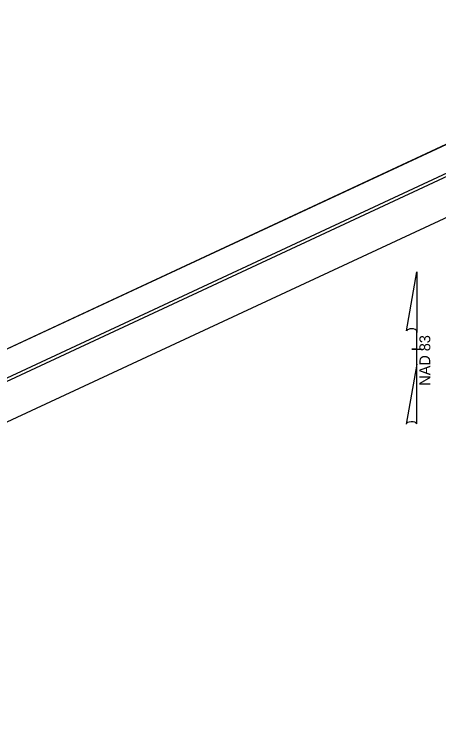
# Model space of a CAD drawing. Extents: x 2321825 to 2323872, y 921700 to 923436.
# Drawn here: x 2322864 to 2323189, y 922857 to 923403 of the extents above; entities that cross this region are included whole.
import ezdxf

# ---------------------------------------------------------------- set-up
doc = ezdxf.new("R2010")
doc.units = 0
for name, color, linetype in [('Prop North Arrow NAD83 for Plan Sheets CELL', 7, 'Continuous'), ('Sheet Cutting Line CELL', 7, 'Continuous'), ('Sheet Layout Plan Border', 7, 'Continuous'), ('Sheet Plan And Profile CELL', 7, 'Continuous'), ('Sheet Plot Border Inside CELL', 7, 'Continuous'), ('Sheet Plot Border Outside CELL', 7, 'Continuous')]:
    doc.layers.add(name, color=color, linetype=linetype)

msp = doc.modelspace()

# ---------------------------------------------------------------- linework, layer by layer
at = {"layer": 'Prop North Arrow NAD83 for Plan Sheets CELL'}
for p, q in [((2323164.49, 923160.58), (2323172.49, 923205.77)), ((2323172.54, 923205.77), (2323172.49, 923205.77)), ((2323172.54, 923205.77), (2323172.49, 923205.77)), ((2323172.54, 923205.77), (2323172.53, 923159.17)), ((2323172.53, 923134.99), (2323172.53, 923160.53)), ((2323172.53, 923159.17), (2323172.53, 923160.49)), ((2323168.63, 923146.3), (2323168.58, 923146.3)), ((2323172.09, 923146.3), (2323168.63, 923146.3)), ((2323168.68, 923146.3), (2323176.48, 923146.3)), ((2323172.53, 923134.99), (2323164.38, 923088.92)), ((2323172.57, 923089.12), (2323172.53, 923134.99))]:
    msp.add_line(p, q, dxfattribs=at)
for centre, start_param, end_param in [((2323168.52, 923160.1), 0.216388, 2.908219), ((2323168.51, 923088.76), 0.201328, 3.141593)]:
    msp.add_ellipse(centre, major_axis=(4.12, -0.03), ratio=0.461098, start_param=start_param, end_param=end_param, dxfattribs=at)
at = {"layer": 'Sheet Cutting Line CELL'}
msp.add_line((2323409.34, 923403.35), (2321883.46, 922692.1), dxfattribs=at)
at = {"layer": 'Sheet Layout Plan Border'}
msp.add_lwpolyline([(2323496.81, 922817.99), (2322321.56, 922264.67), (2322282.6, 922345.71), (2322138.58, 922653.86), (2322100.41, 922737.9), (2323278.09, 923285.95)], close=True, dxfattribs=at)
at = {"layer": 'Sheet Plan And Profile CELL'}
msp.add_lwpolyline([(2323403.44, 923375.77), (2322043.88, 922742.05), (2322487.48, 921790.36), (2323847.04, 922424.08)], close=True, dxfattribs=at)
at = {"layer": 'Sheet Plot Border Inside CELL'}
msp.add_lwpolyline([(2322349.41, 921723.24), (2323859.43, 922427.1), (2323413.71, 923383.32), (2321903.69, 922679.47)], close=True, dxfattribs=at)
at = {"layer": 'Sheet Plot Border Outside CELL'}
msp.add_lwpolyline([(2322346.08, 921699.62), (2323871.95, 922410.87), (2323409.34, 923403.35), (2321883.46, 922692.1)], close=True, dxfattribs=at)

# ---------------------------------------------------------------- texts
at = {"layer": 'Prop North Arrow NAD83 for Plan Sheets CELL'}
msp.add_text('NAD 83', height=8.288, rotation=89.9913, dxfattribs=at).set_placement((2323182.78, 923118.36))

doc.saveas('drawing.dxf')
